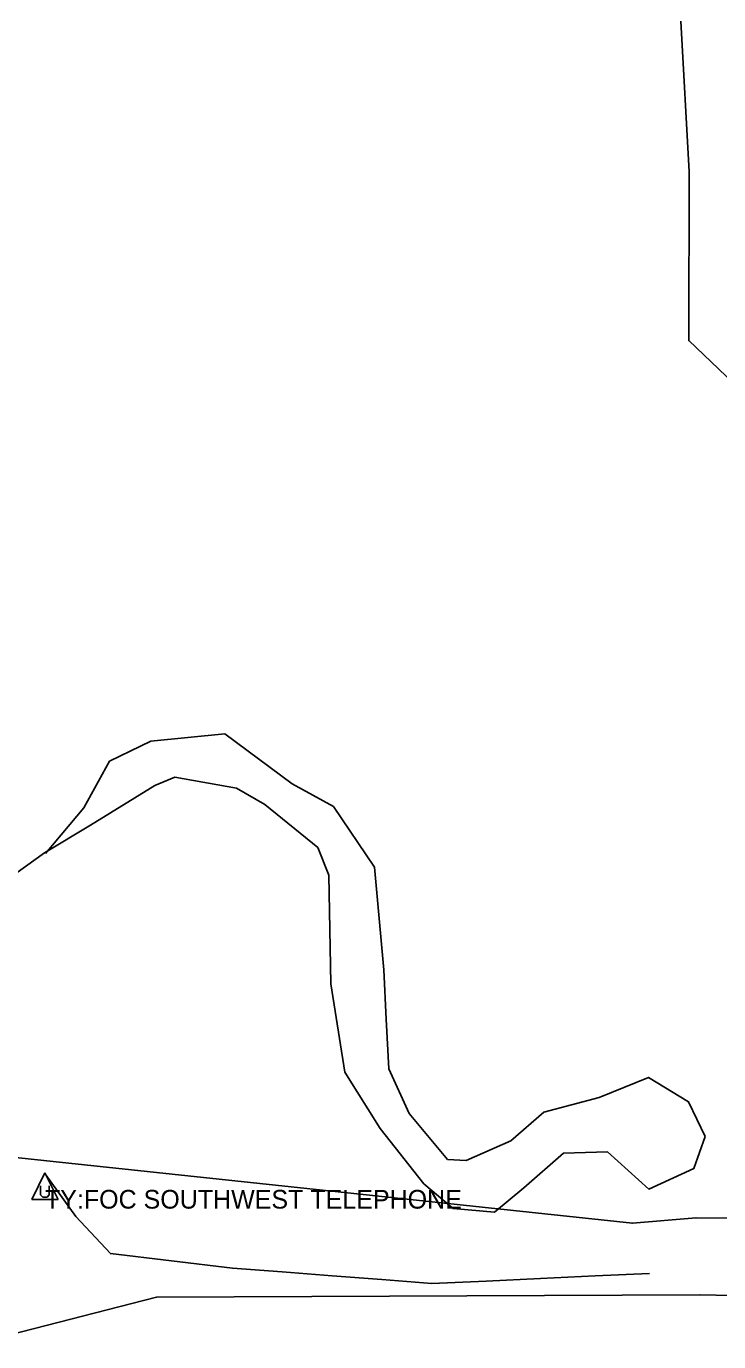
# Model space of a CAD drawing. Extents: x 976456 to 985170, y 1525951 to 1527080.
# Drawn here: x 978068.8 to 978253.9, y 1526548.3 to 1526900 of the extents above; entities that cross this region are included whole.
import ezdxf

# ---------------------------------------------------------------- set-up
doc = ezdxf.new("R2010")
doc.units = 0
for name, color, linetype in [('S_BREAKLINE', 7, 'Continuous'), ('S_DITCHLINE', 7, 'Continuous'), ('S_FENCE', 7, 'Continuous'), ('S_FIBER_OPTIC_CABLE', 7, 'Continuous'), ('S_GRD_PT_SYM', 7, 'Continuous'), ('S_MSC_PT_SYM', 7, 'Continuous'), ('S_STREAM', 7, 'Continuous'), ('S_UNDERGROUND_CABLE', 7, 'Continuous'), ('S_UTILITY_POLE_ANNOT', 7, 'Continuous'), ('S_UTL_PT_SYM', 7, 'Continuous')]:
    doc.layers.add(name, color=color, linetype=linetype)

msp = doc.modelspace()

# ---------------------------------------------------------------- linework, layer by layer
at = {"layer": 'S_BREAKLINE'}
for p, q in [((978245.98, 1526861.12), (978243.75, 1526901.42)), ((978245.87, 1526816.01), (978245.98, 1526861.12)), ((978270.31, 1526792.58), (978245.87, 1526816.01))]:
    msp.add_line(p, q, dxfattribs=at)
at = {"layer": 'S_DITCHLINE'}
msp.add_lwpolyline([(978235.33, 1526566.58), (978220.79, 1526565.9), (978206.24, 1526565.23), (978191.7, 1526564.56), (978177.16, 1526563.89), (978163.83, 1526564.92), (978150.51, 1526565.95), (978137.18, 1526566.98), (978123.86, 1526568.01), (978107.54, 1526569.95), (978091.23, 1526571.89), (978082.03, 1526581.82), (978073.94, 1526592.99)], dxfattribs=at)
at = {"layer": 'S_FENCE'}
for p, q in [((978230.77, 1526580), (977909.7, 1526614.16)), ((978247.82, 1526581.44), (978230.77, 1526580)), ((978318.44, 1526580.95), (978247.82, 1526581.44))]:
    msp.add_line(p, q, dxfattribs=at)
at = {"layer": 'S_FIBER_OPTIC_CABLE'}
for p, q in [((978103.59, 1526560.21), (978057.17, 1526548.34)), ((978248.82, 1526560.85), (978103.59, 1526560.21)), ((978347.23, 1526558.72), (978248.82, 1526560.85))]:
    msp.add_line(p, q, dxfattribs=at)
at = {"layer": 'S_GRD_PT_SYM'}
for points in [[(978245.98, 1526861.12), (978245.98, 1526861.17), (978245.98, 1526861.12), (978245.93, 1526861.12), (978245.98, 1526861.12), (978245.98, 1526861.07), (978245.98, 1526861.12), (978246.03, 1526861.12)], [(978245.87, 1526816.01), (978245.87, 1526816.06), (978245.87, 1526816.01), (978245.82, 1526816.01), (978245.87, 1526816.01), (978245.87, 1526815.96), (978245.87, 1526816.01), (978245.92, 1526816.01)]]:
    msp.add_lwpolyline(points, dxfattribs=at)
at = {"layer": 'S_MSC_PT_SYM'}
for points in [[(978230.77, 1526580), (978230.77, 1526580.05), (978230.77, 1526580), (978230.72, 1526580), (978230.77, 1526580), (978230.77, 1526579.95), (978230.77, 1526580), (978230.82, 1526580)], [(978247.82, 1526581.44), (978247.82, 1526581.49), (978247.82, 1526581.44), (978247.77, 1526581.44), (978247.82, 1526581.44), (978247.82, 1526581.39), (978247.82, 1526581.44), (978247.87, 1526581.44)]]:
    msp.add_lwpolyline(points, dxfattribs=at)
at = {"layer": 'S_STREAM'}
for points in [[(978073.85, 1526678.83), (978084.14, 1526691.1), (978091.01, 1526703.53), (978102.08, 1526708.87), (978121.87, 1526710.85), (978139.85, 1526697.47), (978150.88, 1526691.41), (978161.84, 1526675.22), (978163.08, 1526661.5), (978164.31, 1526647.79), (978164.98, 1526634.55), (978165.64, 1526621.31), (978171.1, 1526609.31), (978181.39, 1526597.03), (978186.36, 1526596.74), (978198.27, 1526602.02), (978207.14, 1526609.72), (978221.92, 1526613.62), (978235.06, 1526618.98), (978245.8, 1526612.48), (978250.21, 1526603.22)], [(978051.61, 1526644.56), (978051.47, 1526656.9), (978056.04, 1526666.46), (978073.63, 1526679.08), (978085.9, 1526686.45), (978103.09, 1526697.07), (978108.45, 1526699.25), (978124.96, 1526696.31), (978132.54, 1526691.99), (978146.67, 1526680.45), (978149.59, 1526673.07), (978149.89, 1526658.56), (978150.2, 1526644.04), (978153.95, 1526620.4), (978163.31, 1526605.37), (978175.04, 1526590.51), (978182.89, 1526583.96), (978193.91, 1526583), (978201.74, 1526589.46), (978212.39, 1526598.76), (978224.11, 1526599.13), (978235.18, 1526589.12), (978247.18, 1526594.64), (978250.22, 1526603.22)]]:
    msp.add_lwpolyline(points, dxfattribs=at)
at = {"layer": 'S_UNDERGROUND_CABLE'}
for p, q in [((978073.74, 1526593.45), (978070.22, 1526586.36)), ((978073.74, 1526593.45), (978077.23, 1526586.36)), ((978072.54, 1526587.6), (978072.54, 1526590.04)), ((978073.16, 1526586.94), (978072.54, 1526587.6)), ((978074.91, 1526587.6), (978074.36, 1526586.94)), ((978074.91, 1526590.04), (978074.91, 1526587.6)), ((978070.22, 1526586.36), (978077.23, 1526586.36)), ((978074.36, 1526586.94), (978073.16, 1526586.94))]:
    msp.add_line(p, q, dxfattribs=at)
at = {"layer": 'S_UTL_PT_SYM'}
for points in [[(978103.59, 1526560.21), (978103.59, 1526560.26), (978103.59, 1526560.21), (978103.54, 1526560.21), (978103.59, 1526560.21), (978103.59, 1526560.16), (978103.59, 1526560.21), (978103.64, 1526560.21)], [(978248.82, 1526560.85), (978248.82, 1526560.9), (978248.82, 1526560.85), (978248.77, 1526560.85), (978248.82, 1526560.85), (978248.82, 1526560.8), (978248.82, 1526560.85), (978248.87, 1526560.85)]]:
    msp.add_lwpolyline(points, dxfattribs=at)

# ---------------------------------------------------------------- texts
at = {"layer": 'S_UTILITY_POLE_ANNOT'}
msp.add_text('TY:FOC SOUTHWEST TELEPHONE', height=5, dxfattribs=at).set_placement((978073.74, 1526583.92))

doc.saveas('drawing.dxf')
